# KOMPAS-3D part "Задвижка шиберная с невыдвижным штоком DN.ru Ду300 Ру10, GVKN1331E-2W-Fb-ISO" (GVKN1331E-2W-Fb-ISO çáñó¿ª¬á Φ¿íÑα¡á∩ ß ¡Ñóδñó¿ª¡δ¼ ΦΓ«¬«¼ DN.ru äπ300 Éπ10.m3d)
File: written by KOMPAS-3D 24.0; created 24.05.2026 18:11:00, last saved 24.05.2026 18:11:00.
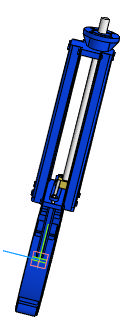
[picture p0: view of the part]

Document properties: Автор: R2D2; Полное имя файла: E:\Работа\Зайцев\GVKN1331E-2W-Fb-ISO Задвижка шиберная с невидвижным штоком DN.ru Ду300 Ру10\GVKN1331E-2W-Fb-ISO Задвижка шиберная с невыдвижным штоком DN.ru Ду300 Ру10.m3d

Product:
- Part/product: Задвижка шиберная с невыдвижным штоком DN.ru Ду300 Ру10  | designation GVKN1331E-2W-Fb-ISO
    Масса: 47.5
    Раздел спецификации: Прочие изделия
    Примечание: D040-08650

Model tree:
1. Операция без истории:1

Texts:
  GVKN1331E-2W-Fb-ISO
